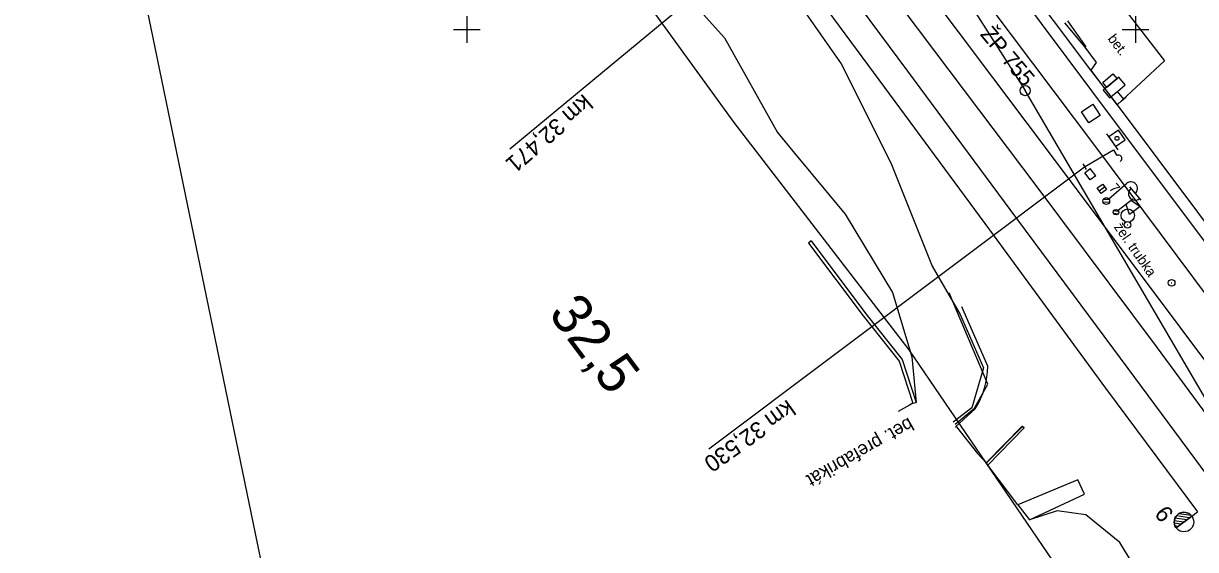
# Model space of a CAD drawing. Extents: x -804166 to -803706, y -1151030 to -1150147.
# Drawn here: x -804166.3 to -803991, y -1150377.7 to -1150299.1 of the extents above; entities that cross this region are included whole.
import ezdxf

# ---------------------------------------------------------------- set-up
doc = ezdxf.new("R2010")
doc.units = 0
for name, color, linetype in [('0381KM032-037P - Vrstva 1', 7, 'Continuous'), ('0381KM032-037P - Vrstva 13', 7, 'Continuous'), ('0381KM032-037P - Vrstva 16', 7, 'Continuous'), ('0381KM032-037P - Vrstva 17', 7, 'Continuous'), ('0381KM032-037P - Vrstva 2', 7, 'Continuous'), ('0381KM032-037P - Vrstva 25', 7, 'Continuous'), ('0381KM032-037P - Vrstva 3', 7, 'Continuous'), ('0381KM032-037P - Vrstva 33', 7, 'Continuous'), ('0381KM032-037P - Vrstva 4', 7, 'Continuous'), ('0381KM032-037P - Vrstva 41', 7, 'Continuous'), ('0381KM032-037P - Vrstva 43', 7, 'Continuous'), ('0381KM032-037P - Vrstva 49', 7, 'Continuous'), ('0381KM032-037P - Vrstva 50', 7, 'Continuous'), ('0381KM032-037P - Vrstva 51', 7, 'Continuous'), ('0381KM032-037P - Vrstva 7', 7, 'Continuous'), ('0381KM032-037P - Vrstva 9', 7, 'Continuous'), ('formát', 7, 'Continuous'), ('hran DP - hran DP', 7, 'Continuous'), ('krizky_1000 - Vrstva 1', 7, 'Continuous'), ('vyt_sit - polygon', 7, 'Continuous'), ('vyt_sit - stávající', 7, 'Continuous')]:
    doc.layers.add(name, color=color, linetype=linetype)

msp = doc.modelspace()

# ---------------------------------------------------------------- linework, layer by layer
at = {"layer": '0381KM032-037P - Vrstva 1'}
for points in [[(-804087.93, -1150205.28), (-804078.71, -1150215.28), (-804072.37, -1150222.52), (-804072.08, -1150222.85), (-804071.47, -1150223.58), (-804065.48, -1150230.82), (-804059.47, -1150238.51), (-804055.55, -1150243.68), (-804054.36, -1150245.27), (-804043.89, -1150259.22), (-804035.37, -1150270.61), (-804034.4, -1150271.93), (-804017.97, -1150293.92), (-804002.6, -1150314.46), (-803985.38, -1150337.43), (-803955.87, -1150376.72)], [(-804089.35, -1150206.44), (-804078.67, -1150220.7), (-804069.15, -1150233.38), (-804067.86, -1150235.11), (-804059.28, -1150246.53), (-804058.07, -1150248.16), (-804048.7, -1150260.65), (-804037.85, -1150275.13), (-804021.63, -1150296.76), (-804006.14, -1150317.34), (-803988.98, -1150340.29), (-803981.9, -1150349.73)], [(-804090.39, -1150214.38), (-804086.65, -1150219.55), (-804073.82, -1150237.11), (-804072.56, -1150238.83), (-804064.05, -1150250.31), (-804062.81, -1150251.97), (-804052.29, -1150266.05), (-804042.5, -1150279.11), (-804026.55, -1150300.33), (-804011.27, -1150320.63), (-803993.37, -1150344.49), (-803965.17, -1150382.07), (-803953.84, -1150397.19)], [(-804093.97, -1150217.42), (-804088.17, -1150225.67), (-804077.51, -1150240.28), (-804068.52, -1150252.21), (-804067.31, -1150253.81), (-804055.01, -1150270.12), (-804046.09, -1150281.93), (-804030.05, -1150303.21), (-804014.76, -1150323.52), (-803996.92, -1150347.35), (-803968.88, -1150385.42), (-803942.6, -1150419.03)], [(-804095.55, -1150218.38), (-804090.74, -1150227.08), (-804084.01, -1150238.21), (-804078.76, -1150245.78), (-804072.11, -1150254.85), (-804070.85, -1150256.55), (-804059.97, -1150271.29), (-804049.56, -1150285.37), (-804034.13, -1150306.22), (-804018.79, -1150326.86), (-804001.18, -1150350.63), (-803980.37, -1150378.68), (-803972.82, -1150388.42), (-803965.21, -1150397.6)], [(-804088.45, -1150239.45), (-804070.36, -1150264.07), (-804054.98, -1150285.05), (-804052.95, -1150287.79), (-804037.56, -1150308.64), (-804021.87, -1150329.91), (-804004.48, -1150353.56), (-803990.76, -1150372.09)]]:
    msp.add_lwpolyline(points, dxfattribs=at)
at = {"layer": '0381KM032-037P - Vrstva 13'}
for p, q in [((-804010.19, -1150298.7), (-804007.43, -1150302.56)), ((-804040.72, -1150342.79), (-804035.37, -1150349.53)), ((-804035.37, -1150349.53), (-804033.33, -1150355.83)), ((-804033.33, -1150355.83), (-804032.83, -1150355.72)), ((-804016.94, -1150359.26), (-804022.35, -1150364.74)), ((-804016.92, -1150359.32), (-804022.32, -1150364.8)), ((-804022.11, -1150365.08), (-804016.66, -1150359.51)), ((-804022.35, -1150364.74), (-804022.32, -1150364.8)), ((-804022.32, -1150364.8), (-804022.11, -1150365.08))]:
    msp.add_line(p, q, dxfattribs=at)
for points in [[(-804048.5, -1150331.59), (-804048.9, -1150331.9), (-804040.72, -1150342.79)], [(-804048.5, -1150331.59), (-804040.34, -1150342.47), (-804034.91, -1150349.29), (-804032.83, -1150355.72)], [(-804033.33, -1150355.83), (-804033.81, -1150356.11), (-804035.52, -1150357.08)], [(-804016.66, -1150359.51), (-804016.92, -1150359.32), (-804016.94, -1150359.26), (-804016.66, -1150359.51)]]:
    msp.add_lwpolyline(points, dxfattribs=at)
at = {"layer": '0381KM032-037P - Vrstva 16'}
for points in [[(-804032.64, -1150269.93), (-804033.34, -1150270.47), (-804023.51, -1150283.74), (-804006.75, -1150306.05), (-804006.63, -1150306.04)], [(-804003.99, -1150293.85), (-803995.7, -1150304.68), (-804002.75, -1150311.23), (-804006.63, -1150306.04), (-804005.86, -1150304.94), (-804007.53, -1150302.64), (-804010.58, -1150299)]]:
    msp.add_lwpolyline(points, dxfattribs=at)
at = {"layer": '0381KM032-037P - Vrstva 17'}
for p, q in [((-804026.76, -1150359.35), (-804023.62, -1150363.33)), ((-804023.62, -1150363.33), (-804022.35, -1150364.74)), ((-804017.62, -1150371.01), (-804022.11, -1150365.08)), ((-804008.64, -1150367.29), (-804017.62, -1150371.01)), ((-804007.64, -1150369.41), (-804008.64, -1150367.29)), ((-804015.88, -1150373.24), (-804007.64, -1150369.41))]:
    msp.add_line(p, q, dxfattribs=at)
for points in [[(-804026.99, -1150358.95), (-804024.09, -1150356.55), (-804022.1, -1150353.01), (-804027.89, -1150339.34)], [(-804026.92, -1150359.34), (-804026.76, -1150359.35)], [(-804017.62, -1150371.01), (-804015.88, -1150373.24)]]:
    msp.add_lwpolyline(points, dxfattribs=at)
at = {"layer": '0381KM032-037P - Vrstva 2'}
for p, q in [((-803991.66, -1150372.63), (-803993.54, -1150372.35)), ((-803991.59, -1150372.71), (-803990.76, -1150372.09)), ((-803992.78, -1150373.6), (-803994.21, -1150373.39)), ((-803993.2, -1150373.92), (-803994.21, -1150373.77)), ((-803992.35, -1150373.28), (-803994.11, -1150373.03)), ((-803993.63, -1150374.24), (-803994.1, -1150374.17)), ((-803991.59, -1150372.71), (-803993.93, -1150374.46)), ((-803993.93, -1150374.46), (-803991.59, -1150372.71)), ((-803991.93, -1150372.97), (-803993.9, -1150372.68)), ((-803991.59, -1150372.71), (-803991.59, -1150372.71))]:
    msp.add_line(p, q, dxfattribs=at)
msp.add_circle((-803992.77, -1150373.59), 1.46, dxfattribs=at)
msp.add_arc((-803992.76, -1150373.59), 1.46, 36.7889, 216.7498, dxfattribs=at)
at = {"layer": '0381KM032-037P - Vrstva 25'}
for p, q in [((-804004.01, -1150325.29), (-804001.36, -1150322.99)), ((-804000.9, -1150323.52), (-803999.2, -1150325.49)), ((-804004.87, -1150325.72), (-804003.91, -1150325.79)), ((-804004.81, -1150325.35), (-804003.93, -1150325.41))]:
    msp.add_line(p, q, dxfattribs=at)
msp.add_lwpolyline([(-804004.28, -1150308.67), (-804004.92, -1150307.91), (-804003.39, -1150306.62), (-804002.75, -1150307.38), (-804004.28, -1150308.67)], dxfattribs=at)
msp.add_circle((-804004.38, -1150325.62), 0.5, dxfattribs=at)
msp.add_circle((-804004.38, -1150325.62), 0.5, dxfattribs=at)
for centre, start, end in [((-804000.71, -1150323.75), 310.9638, 130.9638), ((-804000.06, -1150324.51), 130.2612, 311.6663)]:
    msp.add_arc(centre, 1, start, end, dxfattribs=at)
at = {"layer": '0381KM032-037P - Vrstva 3'}
for p, q in [((-804004.37, -1150315.57), (-804002.64, -1150317.96)), ((-804002.58, -1150315.01), (-804004.02, -1150316.04)), ((-804004.02, -1150316.04), (-804002.99, -1150317.49)), ((-804001.55, -1150316.45), (-804002.58, -1150315.01)), ((-804002.99, -1150317.49), (-804001.55, -1150316.45)), ((-803994.66, -1150337.85), (-803994.56, -1150337.85))]:
    msp.add_line(p, q, dxfattribs=at)
for centre, radius in [((-804002.78, -1150316.25), 0.296), ((-803994.61, -1150337.85), 0.5)]:
    msp.add_circle(centre, radius, dxfattribs=at)
at = {"layer": '0381KM032-037P - Vrstva 33'}
for p, q in [((-804000.39, -1150325.35), (-804002.63, -1150327.02)), ((-804000.93, -1150327.62), (-804001.43, -1150326.12)), ((-803999.33, -1150326.43), (-804000.93, -1150327.62)), ((-804000.63, -1150325.53), (-803999.33, -1150326.43)), ((-804003.3, -1150327.43), (-804002.63, -1150327.53)), ((-804003.25, -1150327.03), (-804002.56, -1150327.14))]:
    msp.add_line(p, q, dxfattribs=at)
msp.add_circle((-804002.93, -1150327.28), 0.401, dxfattribs=at)
msp.add_circle((-804002.93, -1150327.28), 0.401, dxfattribs=at)
at = {"layer": '0381KM032-037P - Vrstva 4'}
msp.add_lwpolyline([(-804033.34, -1150270.47), (-804023.51, -1150283.74), (-804006.75, -1150306.05), (-804002.75, -1150311.23), (-803984.52, -1150335.59), (-803962.04, -1150365.45)], dxfattribs=at)
at = {"layer": '0381KM032-037P - Vrstva 41'}
for p, q in [((-804007.63, -1150320.5), (-804003.32, -1150317.97)), ((-804003.32, -1150317.97), (-804002.82, -1150318.83)), ((-804063.79, -1150362.63), (-804007.63, -1150320.5)), ((-804007.89, -1150320.07), (-804007.38, -1150320.93))]:
    msp.add_line(p, q, dxfattribs=at)
msp.add_lwpolyline([(-804006.41, -1150311.16), (-804005.3, -1150312.82), (-804006.97, -1150313.93), (-804008.08, -1150312.27), (-804006.41, -1150311.16)], dxfattribs=at)
msp.add_arc((-804002.56, -1150319.25), 0.5, 299.3257, 121.6172, dxfattribs=at)
at = {"layer": '0381KM032-037P - Vrstva 43'}
msp.add_line((-804005.93, -1150321.83), (-804006.77, -1150320.75), dxfattribs=at)
for points in [[(-804005.93, -1150321.83), (-804006.79, -1150322.47), (-804007.61, -1150321.38), (-804006.77, -1150320.75)], [(-804005.45, -1150324.07), (-804005.73, -1150323.66), (-804004.91, -1150323.09), (-804004.34, -1150323.91), (-804005.16, -1150324.48), (-804005.45, -1150324.07), (-804004.63, -1150323.5)]]:
    msp.add_lwpolyline(points, dxfattribs=at)
msp.add_circle((-804001.17, -1150327.79), 1, dxfattribs=at)
at = {"layer": '0381KM032-037P - Vrstva 49'}
for p, q in [((-804022.74, -1150350.54), (-804024.47, -1150356.54)), ((-804024.47, -1150356.54), (-804027.3, -1150358.69))]:
    msp.add_line(p, q, dxfattribs=at)
for points in [[(-804119.6, -1150227.37), (-804114.18, -1150233.24), (-804110.61, -1150241.24), (-804107.35, -1150246.09), (-804099.61, -1150256.67), (-804091.21, -1150269.57), (-804073.78, -1150287.54), (-804061.47, -1150301.24), (-804053.54, -1150315.4), (-804051.02, -1150318.44), (-804043.41, -1150327.56), (-804036.34, -1150339.31), (-804033.47, -1150348.91), (-804032.83, -1150355.72)], [(-804067.58, -1150273.2), (-804053.47, -1150291.61), (-804044.04, -1150305.1), (-804036.58, -1150319.92), (-804030.41, -1150335.37), (-804026.23, -1150342.57), (-804022.74, -1150350.54)], [(-803995.51, -1150387.87), (-804002.35, -1150376.64), (-804007.46, -1150372.51), (-804011.72, -1150371.94), (-804015.88, -1150373.24)]]:
    msp.add_lwpolyline(points, dxfattribs=at)
at = {"layer": '0381KM032-037P - Vrstva 50'}
msp.add_line((-804001.26, -1150329.18), (-804001.16, -1150329.18), dxfattribs=at)
msp.add_circle((-804001.21, -1150329.18), 0.5, dxfattribs=at)
at = {"layer": '0381KM032-037P - Vrstva 51'}
for p, q in [((-804002.16, -1150310.7), (-804001.39, -1150310.07)), ((-804022.1, -1150350.3), (-804025.97, -1150341.45)), ((-804026.92, -1150359.34), (-804023.98, -1150356.66))]:
    msp.add_line(p, q, dxfattribs=at)
msp.add_lwpolyline([(-804001.78, -1150310.39), (-804002.73, -1150309.23), (-804001.58, -1150308.27), (-804002.53, -1150307.12), (-804004.85, -1150309.03), (-804003.89, -1150310.19), (-804002.73, -1150309.23)], dxfattribs=at)
msp.add_ellipse((-804033.55, -1150350.88), major_axis=(7.51, 9.2), ratio=0.940819, start_param=4.845934, end_param=5.41758, dxfattribs=at)
at = {"layer": '0381KM032-037P - Vrstva 9'}
msp.add_line((-804041.91, -1150275.08), (-804093.56, -1150317.87), dxfattribs=at)
at = {"layer": 'formát'}
msp.add_line((-804166.3, -1150207.4), (-804123.84, -1150413.06), dxfattribs=at)
at = {"layer": 'hran DP - hran DP'}
for p, q in [((-804060.01, -1150313.9), (-804081.21, -1150284.7)), ((-804033.86, -1150347.88), (-804060.01, -1150313.9)), ((-804004.05, -1150391.51), (-804033.86, -1150347.88))]:
    msp.add_line(p, q, dxfattribs=at)
at = {"layer": 'krizky_1000 - Vrstva 1'}
for points in [[(-804100, -1150298), (-804100, -1150302)], [(-804000, -1150298), (-804000, -1150302)], [(-804102, -1150300), (-804098, -1150300)], [(-804002, -1150300), (-803998, -1150300)]]:
    msp.add_lwpolyline(points, dxfattribs=at)
at = {"layer": 'vyt_sit - polygon'}
for p in [(-804079.95, -1150209.42), (-803955.93, -1150412.63)]:
    msp.add_line(p, (-804016.51, -1150309.12), dxfattribs=at)
at = {"layer": 'vyt_sit - stávající'}
msp.add_line((-804016.56, -1150309.12), (-804016.46, -1150309.12), dxfattribs=at)
msp.add_circle((-804016.51, -1150309.12), 0.756, dxfattribs=at)

# ---------------------------------------------------------------- texts
at = {"layer": '0381KM032-037P - Vrstva 13'}
msp.add_text('bet. prefabrikát', height=2, rotation=209.6616, dxfattribs=at).set_placement((-804033.92, -1150357.9))
at = {"layer": '0381KM032-037P - Vrstva 16'}
msp.add_text('bet.', height=1.5, rotation=307.4446, dxfattribs=at).set_placement((-804004.25, -1150301.38))
at = {"layer": '0381KM032-037P - Vrstva 2'}
msp.add_text('6', height=2.5, rotation=306.7693, dxfattribs=at).set_placement((-803997.29, -1150372.37))
at = {"layer": '0381KM032-037P - Vrstva 25'}
msp.add_text('7', height=1.5, rotation=310.9638, dxfattribs=at).set_placement((-804004.06, -1150323.75))
at = {"layer": '0381KM032-037P - Vrstva 41'}
msp.add_text('km 32,530', height=2.5, rotation=215.4715, dxfattribs=at).set_placement((-804052.06, -1150355.2))
at = {"layer": '0381KM032-037P - Vrstva 50'}
msp.add_text('žel. trubka', height=1.5, rotation=305, dxfattribs=at).set_placement((-804003.31, -1150329.5))
at = {"layer": '0381KM032-037P - Vrstva 7'}
msp.add_text('32,5', height=6, rotation=306.9651, dxfattribs=at).set_placement((-804087.92, -1150342.46))
at = {"layer": '0381KM032-037P - Vrstva 9'}
msp.add_text('km 32,471', height=2.5, rotation=220.7607, dxfattribs=at).set_placement((-804082.58, -1150309.5))
at = {"layer": 'vyt_sit - stávající'}
msp.add_text('ŽP 755', height=2.4, rotation=310, dxfattribs=at).set_placement((-804023.35, -1150300.75))

doc.saveas('drawing.dxf')
